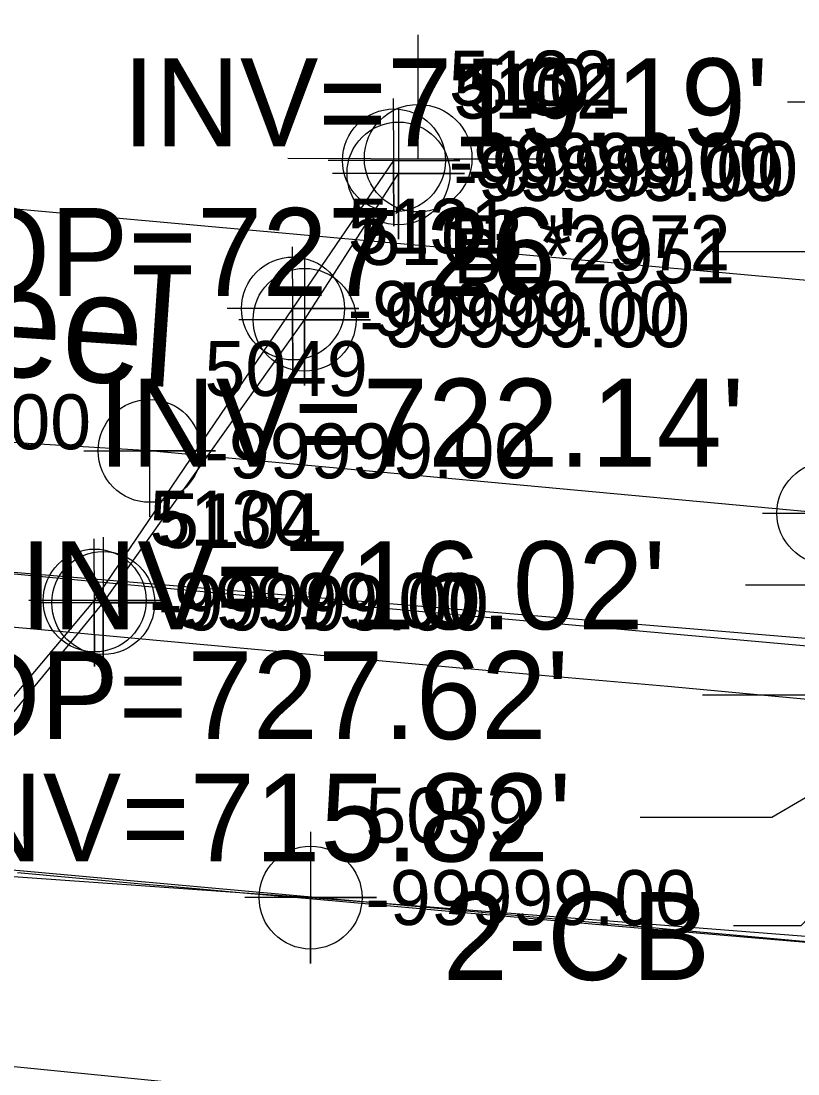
# Model space of a CAD drawing. Extents: x 1516784 to 1522736, y 634838 to 639369.
# Drawn here: x 1520882.23 to 1520917.62, y 638763.8 to 638811.77 of the extents above; entities that cross this region are included whole.
import ezdxf

# ---------------------------------------------------------------- set-up
doc = ezdxf.new("R2010")
doc.units = 0
for name, color, linetype in [('COGO Default Point Elevation', 7, 'Continuous'), ('COGO Default Point Number', 7, 'Continuous'), ('Exist Environmental Wetland Boundary Cogo Number', 7, 'Continuous'), ('Exist Environmental Wetland Boundary Text', 7, 'Continuous'), ('Exist Right of Way Line', 7, 'Continuous'), ('Exist Structure Minor Catch Basin Leader', 7, 'Continuous'), ('Exist Structure Minor Catch Basin Text', 7, 'Continuous'), ('Exist Structure Minor Catch Basin Top Elevation', 7, 'Continuous'), ('Exist Structure Minor Pipes CMP 54 Inch Invert', 7, 'Continuous'), ('Exist Structure Minor Pipes CMP 54 Inch Leader', 7, 'Continuous'), ('Exist Structure Minor Pipes RCP 60 Inch Invert', 7, 'Continuous'), ('Exist Structure Minor Pipes RCP 60 Inch Leader', 7, 'Continuous'), ('Exist Structure Minor Storm Sewer Manhole Leader', 7, 'Continuous'), ('Exist Structure Minor Storm Sewer Manhole Text', 7, 'Continuous'), ('Exist Utilities Gas UG Line SUE LOS B', 7, 'Continuous'), ('Exist Utilities Gas UG Line SUE LOS B Cogo Elevation', 7, 'Continuous'), ('Exist Utilities Gas UG Line SUE LOS B Cogo Number', 7, 'Continuous'), ('Exist Utilities Gas UG Line SUE LOS B Cogo Point CELL', 7, 'Continuous'), ('Exist Utilities Gas UG Line SUE LOS B Text', 7, 'Continuous'), ('Exist Utilities Power Joint Use Telephone CELL', 7, 'Continuous'), ('Exist Utilities Power Pole Cogo Elevation', 7, 'Continuous'), ('Exist Utilities Power Pole Cogo Number', 7, 'Continuous'), ('Exist Utilities Power UG Cable SUE LOS B', 7, 'Continuous'), ('Exist Utilities Power UG Cable SUE LOS B Cogo Comment', 7, 'Continuous'), ('Exist Utilities Power UG Cable SUE LOS B Cogo Elevation', 7, 'Continuous'), ('Exist Utilities Power UG Cable SUE LOS B Cogo Number', 7, 'Continuous'), ('Exist Utilities Power UG Cable SUE LOS B Cogo Point CELL', 7, 'Continuous'), ('Exist Utilities Sanitary Sewer UG Line', 7, 'Continuous'), ('Exist Utilities Telephone UG Conduit SUE LOS B', 7, 'Continuous'), ('Exist Utilities Telephone UG Conduit SUE LOS B Cogo Comment', 7, 'Continuous'), ('Exist Utilities Telephone UG Conduit SUE LOS B Cogo Elevation', 7, 'Continuous'), ('Exist Utilities Telephone UG Conduit SUE LOS B Cogo Number', 7, 'Continuous'), ('Exist Utilities Telephone UG Conduit SUE LOS B Cogo Point CELL', 7, 'Continuous'), ('Exist Utilities Water UG Line SUE LOS B', 7, 'Continuous'), ('Exist Utilities Water UG Line SUE LOS B Cogo Elevation', 7, 'Continuous'), ('Exist Utilities Water UG Line SUE LOS B Cogo Number', 7, 'Continuous'), ('Exist Utilities Water UG Line SUE LOS B Cogo Point CELL', 7, 'Continuous'), ('Exist Utilities Water UG Line SUE LOS C', 7, 'Continuous')]:
    doc.layers.add(name, color=color, linetype=linetype)

msp = doc.modelspace()

# ---------------------------------------------------------------- linework, layer by layer
at = {"layer": 'COGO Default Point Elevation'}
msp.add_lwpolyline([(1520919.066, 638769.702), (1520916.575, 638769.915), (1520914.084, 638770.128), (1520911.593, 638770.341), (1520909.102, 638770.554), (1520907.361, 638770.703), (1520904.871, 638770.926), (1520902.381, 638771.148), (1520899.891, 638771.37), (1520897.402, 638771.592), (1520895.186, 638771.79), (1520892.697, 638772.012), (1520890.207, 638772.233), (1520887.717, 638772.454), (1520885.228, 638772.676), (1520884.568, 638772.734), (1520882.079, 638772.965)], dxfattribs=at)
at = {"layer": 'COGO Default Point Number'}
msp.add_lwpolyline([(1520955.113, 638778.515), (1520953.057, 638778.3), (1520951.157, 638778.238), (1520949.1, 638778.268), (1520946.969, 638778.359), (1520943.117, 638778.649), (1520935.881, 638779.276), (1520929.878, 638779.782), (1520926.459, 638780.082), (1520922.856, 638780.417), (1520916.581, 638780.998), (1520911.693, 638781.45), (1520906.105, 638781.946), (1520900.201, 638782.47), (1520894.364, 638783.007), (1520888.574, 638783.542), (1520882.81, 638784.063), (1520877.016, 638784.586)], dxfattribs=at)
at = {"layer": 'Exist Environmental Wetland Boundary Cogo Number'}
msp.add_lwpolyline([(1520880.788, 638786.686), (1520886.903, 638786.117), (1520892.684, 638785.584), (1520898.132, 638785.088), (1520903.245, 638784.629), (1520913.122, 638783.747), (1520922.964, 638782.868), (1520931.978, 638782.075), (1520939.37, 638781.453), (1520944.595, 638781.025), (1520947.108, 638780.816), (1520948.279, 638780.737), (1520949.484, 638780.699), (1520950.726, 638780.703), (1520952.014, 638780.749), (1520953.313, 638780.839), (1520954.589, 638780.971), (1520955.862, 638781.163)], dxfattribs=at)
at = {"layer": 'Exist Environmental Wetland Boundary Text'}
msp.add_line((1520569.383, 638801.322), (1520948.554, 638767.08), dxfattribs=at)
at = {"layer": 'Exist Right of Way Line'}
msp.add_line((1520625.534, 638826.373), (1520958.512, 638796.302), dxfattribs=at)
at = {"layer": 'Exist Structure Minor Catch Basin Leader'}
for points in [[(1520922.891, 638782.379), (1520919.279, 638781.057), (1520913.279, 638781.057)], [(1520927.79, 638781.018), (1520917.749, 638770.552), (1520914.681, 638770.552)]]:
    msp.add_lwpolyline(points, dxfattribs=at)
at = {"layer": 'Exist Structure Minor Pipes CMP 54 Inch Leader'}
msp.add_lwpolyline([(1520930.046, 638798.08), (1520923.141, 638808.066), (1520917.141, 638808.066)], dxfattribs=at)
at = {"layer": 'Exist Structure Minor Pipes RCP 60 Inch Leader'}
for points in [[(1520925.684, 638782.053), (1520921.239, 638786.064), (1520915.239, 638786.064)], [(1520925.626, 638780.865), (1520916.429, 638775.484), (1520910.429, 638775.484)]]:
    msp.add_lwpolyline(points, dxfattribs=at)
at = {"layer": 'Exist Structure Minor Storm Sewer Manhole Leader'}
msp.add_lwpolyline([(1520927.144, 638795.625), (1520919.718, 638801.25), (1520913.718, 638801.25)], dxfattribs=at)
at = {"layer": 'Exist Utilities Gas UG Line SUE LOS B'}
msp.add_lwpolyline([(1520539.177, 638834.883), (1520564.677, 638828.503), (1520580.047, 638824.156), (1520598.765, 638820.41), (1520612.087, 638817.183), (1520628.437, 638812.308), (1520643.855, 638808.13), (1520657.235, 638806.832), (1520690.694, 638805.095), (1520711.425, 638804.617), (1520742.75, 638803.38), (1520783.344, 638801.18), (1520808.892, 638798.591), (1520838.893, 638796.571), (1520867.952, 638793.415), (1520888.082, 638792.198), (1520918.904, 638789.344), (1520950.661, 638785.177), (1520963.56, 638782.781), (1520974.163, 638781.118)], dxfattribs=at)
at = {"layer": 'Exist Utilities Gas UG Line SUE LOS B Cogo Point CELL'}
for points in [[(1520885.09, 638792.188), (1520891.09, 638792.188), (1520888.09, 638792.188), (1520888.09, 638795.188), (1520888.09, 638789.188)], [(1520916.008, 638789.35), (1520922.008, 638789.35), (1520919.008, 638789.35), (1520919.008, 638792.35), (1520919.008, 638786.35)]]:
    msp.add_lwpolyline(points, dxfattribs=at)
for centre in [(1520888.09, 638792.188), (1520919.008, 638789.35)]:
    msp.add_circle(centre, 2.344, dxfattribs=at)
at = {"layer": 'Exist Utilities Power Joint Use Telephone CELL'}
msp.add_line((1520900.32, 638805.516), (1520900.32, 638805.516), dxfattribs=at)
msp.add_lwpolyline([(1520894.383, 638805.516), (1520905.72, 638805.478), (1520900.32, 638805.496), (1520900.32, 638811.141)], dxfattribs=at)
msp.add_circle((1520900.322, 638805.522), 2.45, dxfattribs=at)
at = {"layer": 'Exist Utilities Power UG Cable SUE LOS B'}
msp.add_lwpolyline([(1520784.113, 638662.494), (1520786.254, 638667.391), (1520795.328, 638678.928), (1520804.538, 638694.542), (1520820.114, 638707.825), (1520836.889, 638721.363), (1520846.968, 638733.099), (1520857.28, 638746.046), (1520866.498, 638761.495), (1520885.977, 638785.26), (1520895.148, 638798.159), (1520899.425, 638804.825)], dxfattribs=at)
at = {"layer": 'Exist Utilities Power UG Cable SUE LOS B Cogo Point CELL'}
for points in [[(1520899.425, 638807.825), (1520899.425, 638801.825), (1520899.425, 638804.825), (1520902.425, 638804.825), (1520896.425, 638804.825)], [(1520895.148, 638801.159), (1520895.148, 638795.159), (1520895.148, 638798.159), (1520898.148, 638798.159), (1520892.148, 638798.159)], [(1520885.977, 638788.26), (1520885.977, 638782.26), (1520885.977, 638785.26), (1520888.977, 638785.26), (1520882.977, 638785.26)]]:
    msp.add_lwpolyline(points, dxfattribs=at)
for centre in [(1520899.425, 638804.825), (1520895.148, 638798.159), (1520885.977, 638785.26)]:
    msp.add_circle(centre, 2.344, dxfattribs=at)
at = {"layer": 'Exist Utilities Sanitary Sewer UG Line'}
msp.add_line((1520764.792, 638775.768), (1520964.322, 638755.964), dxfattribs=at)
at = {"layer": 'Exist Utilities Telephone UG Conduit SUE LOS B'}
msp.add_lwpolyline([(1520767.023, 638629.297), (1520780.833, 638626.694), (1520783.044, 638628.355), (1520786.921, 638649.642), (1520789.694, 638665.851), (1520794.358, 638679.365), (1520803.878, 638695.098), (1520819.519, 638708.633), (1520836.327, 638722.159), (1520846.505, 638733.886), (1520856.458, 638746.655), (1520865.818, 638761.863), (1520885.587, 638785.372), (1520894.619, 638798.674), (1520899.221, 638805.419)], dxfattribs=at)
at = {"layer": 'Exist Utilities Telephone UG Conduit SUE LOS B Cogo Point CELL'}
for points in [[(1520899.188, 638808.233), (1520899.221, 638802.419), (1520899.204, 638805.419), (1520902.221, 638805.419), (1520896.221, 638805.419)], [(1520894.586, 638801.489), (1520894.619, 638795.674), (1520894.602, 638798.674), (1520897.619, 638798.674), (1520891.619, 638798.674)], [(1520885.554, 638788.187), (1520885.587, 638782.372), (1520885.57, 638785.372), (1520888.587, 638785.372), (1520882.587, 638785.372)]]:
    msp.add_lwpolyline(points, dxfattribs=at)
for centre in [(1520899.221, 638805.419), (1520894.619, 638798.674), (1520885.587, 638785.372)]:
    msp.add_circle(centre, 2.344, dxfattribs=at)
at = {"layer": 'Exist Utilities Water UG Line SUE LOS B'}
msp.add_lwpolyline([(1520620.203, 638809.209), (1520630.943, 638807.88), (1520658.415, 638805.133), (1520674.915, 638803.909), (1520684.211, 638796.868), (1520692.994, 638790.385), (1520732.672, 638785.819), (1520762.877, 638782.344), (1520795.433, 638778.959), (1520828.599, 638776.457), (1520864.457, 638774.03), (1520895.421, 638771.84), (1520928.873, 638769.232), (1520958.885, 638767.555), (1520974.968, 638766.605)], dxfattribs=at)
at = {"layer": 'Exist Utilities Water UG Line SUE LOS B Cogo Point CELL'}
msp.add_lwpolyline([(1520895.421, 638774.84), (1520895.421, 638768.84), (1520895.421, 638771.84), (1520898.421, 638771.84), (1520892.421, 638771.84)], dxfattribs=at)
msp.add_circle((1520895.421, 638771.84), 2.344, dxfattribs=at)
at = {"layer": 'Exist Utilities Water UG Line SUE LOS C'}
msp.add_line((1520674.915, 638803.909), (1520974.617, 638778.939), dxfattribs=at)

# ---------------------------------------------------------------- texts
at = {"layer": 'Exist Structure Minor Catch Basin Text'}
msp.add_text('2-CB', height=4, dxfattribs=at).set_placement((1520901.436, 638768.086))
at = {"layer": 'Exist Structure Minor Catch Basin Top Elevation'}
msp.add_text("TOP=727.62'", height=4, dxfattribs=at).set_placement((1520875.689, 638779.057))
at = {"layer": 'Exist Structure Minor Pipes CMP 54 Inch Invert'}
msp.add_text("INV=719.19'", height=4, dxfattribs=at).set_placement((1520886.857, 638806.066))
at = {"layer": 'Exist Structure Minor Pipes RCP 60 Inch Invert'}
for s, p in [("INV=722.14'", (1520885.753, 638791.476)), ("INV=716.02'", (1520882.184, 638784.064)), ("INV=715.82'", (1520877.878, 638773.484))]:
    msp.add_text(s, height=4, dxfattribs=at).set_placement(p)
at = {"layer": 'Exist Structure Minor Storm Sewer Manhole Text'}
msp.add_text("TOP=727.26'", height=4, dxfattribs=at).set_placement((1520876.127, 638799.25))
at = {"layer": 'Exist Utilities Gas UG Line SUE LOS B Cogo Elevation'}
for p in [(1520870.366, 638792.263), (1520890.59, 638790.938)]:
    msp.add_text('-99999.00', height=2.5, dxfattribs=at).set_placement(p)
at = {"layer": 'Exist Utilities Gas UG Line SUE LOS B Cogo Number'}
msp.add_text('5049', height=2.5, dxfattribs=at).set_placement((1520890.59, 638794.688))
at = {"layer": 'Exist Utilities Gas UG Line SUE LOS B Text'}
msp.add_text('Public Service Company Of N C Inc., 2 ", Steel', height=5, rotation=356.1474, dxfattribs=at).set_placement((1520751.087, 638804.382))
at = {"layer": 'Exist Utilities Power Pole Cogo Elevation'}
msp.add_text('-99999.00', height=2.5, dxfattribs=at).set_placement((1520902.564, 638803.803))
at = {"layer": 'Exist Utilities Power Pole Cogo Number'}
msp.add_text('5101', height=2.5, dxfattribs=at).set_placement((1520902.564, 638807.553))
at = {"layer": 'Exist Utilities Power UG Cable SUE LOS B Cogo Comment'}
msp.add_text('BL*2951', height=2.5, dxfattribs=at).set_placement((1520901.925, 638799.825))
at = {"layer": 'Exist Utilities Power UG Cable SUE LOS B Cogo Elevation'}
for p in [(1520901.925, 638803.575), (1520897.648, 638796.909), (1520888.477, 638784.01)]:
    msp.add_text('-99999.00', height=2.5, dxfattribs=at).set_placement(p)
at = {"layer": 'Exist Utilities Power UG Cable SUE LOS B Cogo Number'}
for s, p in [('5102', (1520901.925, 638807.325)), ('5103', (1520897.648, 638800.659)), ('5104', (1520888.477, 638787.76))]:
    msp.add_text(s, height=2.5, dxfattribs=at).set_placement(p)
at = {"layer": 'Exist Utilities Telephone UG Conduit SUE LOS B Cogo Comment'}
msp.add_text('EL*2972', height=2.5, dxfattribs=at).set_placement((1520901.721, 638800.419))
at = {"layer": 'Exist Utilities Telephone UG Conduit SUE LOS B Cogo Elevation'}
for p in [(1520901.721, 638804.169), (1520897.119, 638797.424), (1520888.087, 638784.122)]:
    msp.add_text('-99999.00', height=2.5, dxfattribs=at).set_placement(p)
at = {"layer": 'Exist Utilities Telephone UG Conduit SUE LOS B Cogo Number'}
for s, p in [('5132', (1520901.721, 638807.919)), ('5131', (1520897.119, 638801.174)), ('5130', (1520888.087, 638787.872))]:
    msp.add_text(s, height=2.5, dxfattribs=at).set_placement(p)
at = {"layer": 'Exist Utilities Water UG Line SUE LOS B Cogo Elevation'}
msp.add_text('-99999.00', height=2.5, dxfattribs=at).set_placement((1520897.921, 638770.59))
at = {"layer": 'Exist Utilities Water UG Line SUE LOS B Cogo Number'}
msp.add_text('5059', height=2.5, dxfattribs=at).set_placement((1520897.921, 638774.34))

doc.saveas('drawing.dxf')
